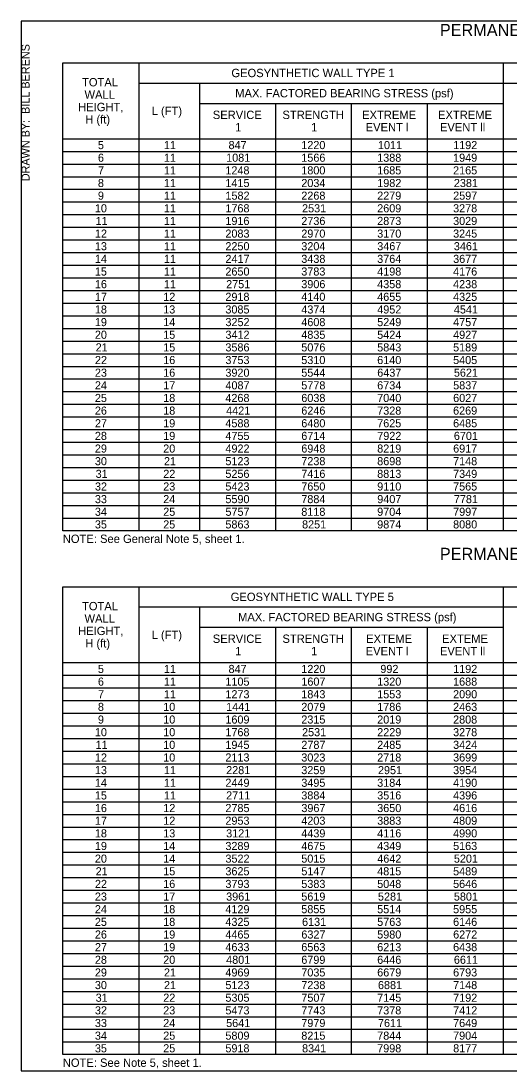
# Model space of a CAD drawing. Extents: x 99862 to 103151, y 100000 to 111076.
# Drawn here: x 99862 to 100828, y 106000 to 108076 of the extents above; entities that cross this region are included whole.
import ezdxf

# ---------------------------------------------------------------- set-up
doc = ezdxf.new("R2010")
doc.units = 0
for name, color, linetype in [('Level 1', 7, 'Continuous'), ('Level 20', 7, 'Continuous'), ('Level 40', 7, 'Continuous'), ('Level 60', 7, 'Continuous'), ('Level 62', 7, 'Continuous')]:
    doc.layers.add(name, color=color, linetype=linetype)

msp = doc.modelspace()

# ---------------------------------------------------------------- linework, layer by layer
at = {"layer": 'Level 1'}
msp.add_lwpolyline([(99862, 105999.5), (103151, 105999.5), (103151, 108075.5), (99862, 108075.5)], close=True, dxfattribs=at)
at = {"layer": 'Level 40'}
for p, q in [((100094.6, 107992.7), (100094.6, 107067.7)), ((100814.6, 107992.7), (100814.6, 107067.7)), ((100094.6, 107952.7), (102524.6, 107952.7)), ((100214.6, 107952.7), (100214.6, 107067.7)), ((100214.6, 107912.7), (100814.6, 107912.7)), ((100364.6, 107912.7), (100364.6, 107067.7)), ((100514.6, 107912.7), (100514.6, 107067.7)), ((100664.6, 107912.7), (100664.6, 107067.7)), ((99944.6, 107842.7), (102524.6, 107842.7)), ((99944.6, 107817.7), (102524.6, 107817.7)), ((99944.6, 107792.7), (102524.6, 107792.7)), ((99944.6, 107767.7), (102524.6, 107767.7)), ((99944.6, 107742.7), (102524.6, 107742.7)), ((99944.6, 107717.7), (102524.6, 107717.7)), ((99944.6, 107692.7), (102524.6, 107692.7)), ((99944.6, 107667.7), (102524.6, 107667.7)), ((99944.6, 107642.7), (102524.6, 107642.7)), ((99944.6, 107617.7), (102524.6, 107617.7)), ((99944.6, 107592.7), (102524.6, 107592.7)), ((99944.6, 107567.7), (102524.6, 107567.7)), ((99944.6, 107542.7), (102524.6, 107542.7)), ((99944.6, 107517.7), (102524.6, 107517.7)), ((99944.6, 107492.7), (102524.6, 107492.7)), ((99944.6, 107467.7), (102524.6, 107467.7)), ((99944.6, 107442.7), (102524.6, 107442.7)), ((99944.6, 107417.7), (102524.6, 107417.7)), ((99944.6, 107392.7), (102524.6, 107392.7)), ((99944.6, 107367.7), (102524.6, 107367.7)), ((99944.6, 107342.7), (102524.6, 107342.7)), ((99944.6, 107317.7), (102524.6, 107317.7)), ((99944.6, 107292.7), (102524.6, 107292.7)), ((99944.6, 107267.7), (102524.6, 107267.7)), ((99944.6, 107242.7), (102524.6, 107242.7)), ((99944.6, 107217.7), (102524.6, 107217.7)), ((99944.6, 107192.7), (102524.6, 107192.7)), ((99944.6, 107167.7), (102524.6, 107167.7)), ((99944.6, 107142.7), (102524.6, 107142.7)), ((99944.6, 107117.7), (102524.6, 107117.7)), ((99944.6, 107092.7), (102524.6, 107092.7)), ((100094.6, 106956.9), (100094.6, 106031.9)), ((100814.6, 106956.9), (100814.6, 106031.9)), ((100094.6, 106916.9), (102524.6, 106916.9)), ((100214.6, 106916.9), (100214.6, 106031.9)), ((100214.6, 106876.9), (100814.6, 106876.9)), ((100364.6, 106876.9), (100364.6, 106031.9)), ((100514.6, 106876.9), (100514.6, 106031.9)), ((100664.6, 106876.9), (100664.6, 106031.9)), ((99944.6, 106806.9), (102524.6, 106806.9)), ((99944.6, 106781.9), (102524.6, 106781.9)), ((99944.6, 106756.9), (102524.6, 106756.9)), ((99944.6, 106731.9), (102524.6, 106731.9)), ((99944.6, 106706.9), (102524.6, 106706.9)), ((99944.6, 106681.9), (102524.6, 106681.9)), ((99944.6, 106656.9), (102524.6, 106656.9)), ((99944.6, 106631.9), (102524.6, 106631.9)), ((99944.6, 106606.9), (102524.6, 106606.9)), ((99944.6, 106581.9), (102524.6, 106581.9)), ((99944.6, 106556.9), (102524.6, 106556.9)), ((99944.6, 106531.9), (102524.6, 106531.9)), ((99944.6, 106506.9), (102524.6, 106506.9)), ((99944.6, 106481.9), (102524.6, 106481.9)), ((99944.6, 106456.9), (102524.6, 106456.9)), ((99944.6, 106431.9), (102524.6, 106431.9)), ((99944.6, 106406.9), (102524.6, 106406.9)), ((99944.6, 106381.9), (102524.6, 106381.9)), ((99944.6, 106356.9), (102524.6, 106356.9)), ((99944.6, 106331.9), (102524.6, 106331.9)), ((99944.6, 106306.9), (102524.6, 106306.9)), ((99944.6, 106281.9), (102524.6, 106281.9)), ((99944.6, 106256.9), (102524.6, 106256.9)), ((99944.6, 106231.9), (102524.6, 106231.9)), ((99944.6, 106206.9), (102524.6, 106206.9)), ((99944.6, 106181.9), (102524.6, 106181.9)), ((99944.6, 106156.9), (102524.6, 106156.9)), ((99944.6, 106131.9), (102524.6, 106131.9)), ((99944.6, 106106.9), (102524.6, 106106.9)), ((99944.6, 106081.9), (102524.6, 106081.9)), ((99944.6, 106056.9), (102524.6, 106056.9))]:
    msp.add_line(p, q, dxfattribs=at)
for points in [[(99944.6, 107992.7), (102524.6, 107992.7), (102524.6, 107067.7), (99944.6, 107067.7)], [(99944.6, 106956.9), (102524.6, 106956.9), (102524.6, 106031.9), (99944.6, 106031.9)]]:
    msp.add_lwpolyline(points, close=True, dxfattribs=at)
at = {"layer": 'Level 60'}
msp.add_line((99862, 105999.5), (99862, 105999.5), dxfattribs=at)

# ---------------------------------------------------------------- texts
at = {"layer": 'Level 20'}
for s, height, p in [('PERMANENT GEOSYNTHETIC WALL - EXTERNAL STABILITY DESIGN', 24, (100689.7, 108045.7)), ('GEOSYNTHETIC WALL TYPE 1', 16.5, (100277.8, 107964.5)), ('TOTAL', 16.5, (99982.6, 107946.2)), ('WALL', 16.5, (99987.5, 107921.7)), ('MAX. FACTORED BEARING STRESS (psf)', 16.5, (100285.3, 107924.5)), ('HEIGHT,', 16.5, (99974.9, 107897.2)), ('H (ft)', 16.5, (99989, 107872.7)), ('L (FT)', 16.5, (100120.2, 107889.5)), ('SERVICE', 16.5, (100241, 107881.7)), ('STRENGTH', 16.5, (100378.7, 107881.7)), ('EXTREME', 16.5, (100536.1, 107881.7)), ('EXTREME', 16.5, (100686.1, 107881.7)), ('1', 16.5, (100285.2, 107857.2)), ('1', 16.5, (100435.2, 107857.2)), ('EVENT l', 16.5, (100543.1, 107857.2)), ('EVENT ll', 16.5, (100689.9, 107857.2)), ('5', 16, (100014, 107822.2)), ('11', 16, (100144.5, 107822.2)), ('847', 16, (100272.1, 107822.2)), ('1220', 16, (100415.9, 107822.2)), ('1011', 16, (100567.4, 107822.2)), ('1192', 16, (100716, 107822.2)), ('6', 16, (100014, 107797.2)), ('11', 16, (100144.5, 107797.2)), ('1081', 16, (100267.4, 107797.2)), ('1566', 16, (100415.9, 107797.2)), ('1388', 16, (100565.9, 107797.2)), ('1949', 16, (100715.9, 107797.2)), ('7', 16, (100014.2, 107772.2)), ('11', 16, (100144.5, 107772.2)), ('1248', 16, (100265.9, 107772.2)), ('1800', 16, (100415.9, 107772.2)), ('1685', 16, (100565.9, 107772.2)), ('2165', 16, (100715.9, 107772.2)), ('8', 16, (100014, 107747.2)), ('11', 16, (100144.5, 107747.2)), ('1415', 16, (100265.9, 107747.2)), ('2034', 16, (100415.9, 107747.2)), ('1982', 16, (100566, 107747.2)), ('2381', 16, (100717.4, 107747.2)), ('9', 16, (100014, 107722.2)), ('11', 16, (100144.5, 107722.2)), ('1582', 16, (100266, 107722.2)), ('2268', 16, (100415.9, 107722.2)), ('2279', 16, (100565.9, 107722.2)), ('2597', 16, (100716, 107722.2)), ('10', 16, (100008, 107697.2)), ('11', 16, (100144.5, 107697.2)), ('1768', 16, (100265.9, 107697.2)), ('2531', 16, (100417.4, 107697.2)), ('2609', 16, (100565.9, 107697.2)), ('3278', 16, (100715.9, 107697.2)), ('11', 16, (100009.5, 107672.2)), ('11', 16, (100144.5, 107672.2)), ('1916', 16, (100265.9, 107672.2)), ('2736', 16, (100415.9, 107672.2)), ('2873', 16, (100565.9, 107672.2)), ('3029', 16, (100715.9, 107672.2)), ('12', 16, (100008.1, 107647.2)), ('11', 16, (100144.5, 107647.2)), ('2083', 16, (100265.9, 107647.2)), ('2970', 16, (100415.9, 107647.2)), ('3170', 16, (100565.9, 107647.2)), ('3245', 16, (100715.9, 107647.2)), ('13', 16, (100008, 107622.2)), ('11', 16, (100144.5, 107622.2)), ('2250', 16, (100265.9, 107622.2)), ('3204', 16, (100415.9, 107622.2)), ('3467', 16, (100566, 107622.2)), ('3461', 16, (100717.4, 107622.2)), ('14', 16, (100008, 107597.2)), ('11', 16, (100144.5, 107597.2)), ('2417', 16, (100266, 107597.2)), ('3438', 16, (100415.9, 107597.2)), ('3764', 16, (100565.9, 107597.2)), ('3677', 16, (100716, 107597.2)), ('15', 16, (100008, 107572.2)), ('11', 16, (100144.5, 107572.2)), ('2650', 16, (100265.9, 107572.2)), ('3783', 16, (100415.9, 107572.2)), ('4198', 16, (100565.9, 107572.2)), ('4176', 16, (100715.9, 107572.2)), ('16', 16, (100008, 107547.2)), ('11', 16, (100144.5, 107547.2)), ('2751', 16, (100267.4, 107547.2)), ('3906', 16, (100415.9, 107547.2)), ('4358', 16, (100565.9, 107547.2)), ('4238', 16, (100715.9, 107547.2)), ('17', 16, (100008.1, 107522.2)), ('12', 16, (100143.1, 107522.2)), ('2918', 16, (100265.9, 107522.2)), ('4140', 16, (100415.9, 107522.2)), ('4655', 16, (100565.9, 107522.2)), ('4325', 16, (100715.9, 107522.2)), ('18', 16, (100008, 107497.2)), ('13', 16, (100143, 107497.2)), ('3085', 16, (100265.9, 107497.2)), ('4374', 16, (100415.9, 107497.2)), ('4952', 16, (100566, 107497.2)), ('4541', 16, (100717.4, 107497.2)), ('19', 16, (100008, 107472.2)), ('14', 16, (100143, 107472.2)), ('3252', 16, (100266, 107472.2)), ('4608', 16, (100415.9, 107472.2)), ('5249', 16, (100565.9, 107472.2)), ('4757', 16, (100716, 107472.2)), ('20', 16, (100008, 107447.2)), ('15', 16, (100143, 107447.2)), ('3412', 16, (100266, 107447.2)), ('4835', 16, (100415.9, 107447.2)), ('5424', 16, (100565.9, 107447.2)), ('4927', 16, (100716, 107447.2)), ('21', 16, (100009.5, 107422.2)), ('15', 16, (100143, 107422.2)), ('3586', 16, (100265.9, 107422.2)), ('5076', 16, (100415.9, 107422.2)), ('5843', 16, (100565.9, 107422.2)), ('5189', 16, (100715.9, 107422.2)), ('22', 16, (100008.1, 107397.2)), ('16', 16, (100143, 107397.2)), ('3753', 16, (100265.9, 107397.2)), ('5310', 16, (100415.9, 107397.2)), ('6140', 16, (100565.9, 107397.2)), ('5405', 16, (100715.9, 107397.2)), ('23', 16, (100008, 107372.2)), ('16', 16, (100143, 107372.2)), ('3920', 16, (100265.9, 107372.2)), ('5544', 16, (100415.9, 107372.2)), ('6437', 16, (100566, 107372.2)), ('5621', 16, (100717.4, 107372.2)), ('24', 16, (100008, 107347.2)), ('17', 16, (100143.1, 107347.2)), ('4087', 16, (100266, 107347.2)), ('5778', 16, (100415.9, 107347.2)), ('6734', 16, (100565.9, 107347.2)), ('5837', 16, (100716, 107347.2)), ('25', 16, (100008, 107322.2)), ('18', 16, (100143, 107322.2)), ('4268', 16, (100265.9, 107322.2)), ('6038', 16, (100415.9, 107322.2)), ('7040', 16, (100565.9, 107322.2)), ('6027', 16, (100716, 107322.2)), ('26', 16, (100008, 107297.2)), ('18', 16, (100143, 107297.2)), ('4421', 16, (100267.4, 107297.2)), ('6246', 16, (100415.9, 107297.2)), ('7328', 16, (100565.9, 107297.2)), ('6269', 16, (100715.9, 107297.2)), ('27', 16, (100008.1, 107272.2)), ('19', 16, (100143, 107272.2)), ('4588', 16, (100265.9, 107272.2)), ('6480', 16, (100415.9, 107272.2)), ('7625', 16, (100565.9, 107272.2)), ('6485', 16, (100715.9, 107272.2)), ('28', 16, (100008, 107247.2)), ('19', 16, (100143, 107247.2)), ('4755', 16, (100265.9, 107247.2)), ('6714', 16, (100415.9, 107247.2)), ('7922', 16, (100566, 107247.2)), ('6701', 16, (100717.4, 107247.2)), ('29', 16, (100008, 107222.2)), ('20', 16, (100143, 107222.2)), ('4922', 16, (100266, 107222.2)), ('6948', 16, (100415.9, 107222.2)), ('8219', 16, (100565.9, 107222.2)), ('6917', 16, (100716, 107222.2)), ('30', 16, (100008, 107197.2)), ('21', 16, (100144.5, 107197.2)), ('5123', 16, (100265.9, 107197.2)), ('7238', 16, (100415.9, 107197.2)), ('8698', 16, (100565.9, 107197.2)), ('7148', 16, (100715.9, 107197.2)), ('31', 16, (100009.5, 107172.2)), ('22', 16, (100143.1, 107172.2)), ('5256', 16, (100265.9, 107172.2)), ('7416', 16, (100415.9, 107172.2)), ('8813', 16, (100565.9, 107172.2)), ('7349', 16, (100715.9, 107172.2)), ('32', 16, (100008.1, 107147.2)), ('23', 16, (100143, 107147.2)), ('5423', 16, (100265.9, 107147.2)), ('7650', 16, (100415.9, 107147.2)), ('9110', 16, (100565.9, 107147.2)), ('7565', 16, (100715.9, 107147.2)), ('33', 16, (100008, 107122.2)), ('24', 16, (100143, 107122.2)), ('5590', 16, (100265.9, 107122.2)), ('7884', 16, (100415.9, 107122.2)), ('9407', 16, (100566, 107122.2)), ('7781', 16, (100717.4, 107122.2)), ('34', 16, (100008, 107097.2)), ('25', 16, (100143, 107097.2)), ('5757', 16, (100266, 107097.2)), ('8118', 16, (100415.9, 107097.2)), ('9704', 16, (100565.9, 107097.2)), ('7997', 16, (100716, 107097.2)), ('35', 16, (100008, 107072.2)), ('25', 16, (100143, 107072.2)), ('5863', 16, (100265.9, 107072.2)), ('8251', 16, (100417.4, 107072.2)), ('9874', 16, (100565.9, 107072.2)), ('8080', 16, (100715.9, 107072.2)), ('NOTE: See General Note 5, sheet 1.', 16.5, (99944.6, 107043.5)), ('PERMANENT GEOSYNTHETIC WALL - EXTERNAL STABILITY DESIGN', 24, (100689.7, 107009.9)), ('GEOSYNTHETIC WALL TYPE 5', 16.5, (100276.4, 106928.7)), ('TOTAL', 16.5, (99982.6, 106910.4)), ('WALL', 16.5, (99987.5, 106885.9)), ('MAX. FACTORED BEARING STRESS (psf)', 16.5, (100291, 106888.7)), ('HEIGHT,', 16.5, (99974.9, 106861.4)), ('H (ft)', 16.5, (99989, 106836.9)), ('L (FT)', 16.5, (100120.2, 106853.7)), ('SERVICE', 16.5, (100241, 106845.9)), ('STRENGTH', 16.5, (100378.7, 106845.9)), ('EXTEME', 16.5, (100544.1, 106845.9)), ('EXTEME', 16.5, (100694.1, 106845.9)), ('1', 16.5, (100285.2, 106821.4)), ('1', 16.5, (100435.2, 106821.4)), ('EVENT l', 16.5, (100543.1, 106821.4)), ('EVENT ll', 16.5, (100689.9, 106821.4)), ('5', 16, (100014, 106786.4)), ('11', 16, (100144.5, 106786.4)), ('847', 16, (100272.1, 106786.4)), ('1220', 16, (100415.9, 106786.4)), ('992', 16, (100572.1, 106786.4)), ('1192', 16, (100716, 106786.4)), ('6', 16, (100014, 106761.4)), ('11', 16, (100144.5, 106761.4)), ('1105', 16, (100265.9, 106761.4)), ('1607', 16, (100416, 106761.4)), ('1320', 16, (100565.9, 106761.4)), ('1688', 16, (100715.9, 106761.4)), ('7', 16, (100014.2, 106736.4)), ('11', 16, (100144.5, 106736.4)), ('1273', 16, (100265.9, 106736.4)), ('1843', 16, (100415.9, 106736.4)), ('1553', 16, (100565.9, 106736.4)), ('2090', 16, (100715.9, 106736.4)), ('8', 16, (100014, 106711.4)), ('10', 16, (100143, 106711.4)), ('1441', 16, (100267.4, 106711.4)), ('2079', 16, (100415.9, 106711.4)), ('1786', 16, (100565.9, 106711.4)), ('2463', 16, (100715.9, 106711.4)), ('9', 16, (100014, 106686.4)), ('10', 16, (100143, 106686.4)), ('1609', 16, (100265.9, 106686.4)), ('2315', 16, (100415.9, 106686.4)), ('2019', 16, (100565.9, 106686.4)), ('2808', 16, (100715.9, 106686.4)), ('10', 16, (100008, 106661.4)), ('10', 16, (100143, 106661.4)), ('1768', 16, (100265.9, 106661.4)), ('2531', 16, (100417.4, 106661.4)), ('2229', 16, (100565.9, 106661.4)), ('3278', 16, (100715.9, 106661.4)), ('11', 16, (100009.5, 106636.4)), ('10', 16, (100143, 106636.4)), ('1945', 16, (100265.9, 106636.4)), ('2787', 16, (100416, 106636.4)), ('2485', 16, (100565.9, 106636.4)), ('3424', 16, (100715.9, 106636.4)), ('12', 16, (100008.1, 106611.4)), ('10', 16, (100143, 106611.4)), ('2113', 16, (100265.9, 106611.4)), ('3023', 16, (100415.9, 106611.4)), ('2718', 16, (100565.9, 106611.4)), ('3699', 16, (100715.9, 106611.4)), ('13', 16, (100008, 106586.4)), ('2281', 16, (100267.4, 106586.4)), ('3259', 16, (100415.9, 106586.4)), ('2951', 16, (100567.4, 106586.4)), ('3954', 16, (100715.9, 106586.4)), ('11', 16, (100144.5, 106586.4)), ('14', 16, (100008, 106561.4)), ('11', 16, (100144.5, 106561.4)), ('2449', 16, (100265.9, 106561.4)), ('3495', 16, (100415.9, 106561.4)), ('3184', 16, (100565.9, 106561.4)), ('4190', 16, (100715.9, 106561.4)), ('15', 16, (100008, 106536.4)), ('11', 16, (100144.5, 106536.4)), ('2711', 16, (100267.4, 106536.4)), ('3884', 16, (100415.9, 106536.4)), ('3516', 16, (100565.9, 106536.4)), ('4396', 16, (100715.9, 106536.4)), ('16', 16, (100008, 106511.4)), ('12', 16, (100143.1, 106511.4)), ('2785', 16, (100265.9, 106511.4)), ('3967', 16, (100416, 106511.4)), ('3650', 16, (100565.9, 106511.4)), ('4616', 16, (100715.9, 106511.4)), ('17', 16, (100008.1, 106486.4)), ('12', 16, (100143.1, 106486.4)), ('2953', 16, (100265.9, 106486.4)), ('4203', 16, (100415.9, 106486.4)), ('3883', 16, (100565.9, 106486.4)), ('4809', 16, (100715.9, 106486.4)), ('18', 16, (100008, 106461.4)), ('13', 16, (100143, 106461.4)), ('3121', 16, (100267.4, 106461.4)), ('4439', 16, (100415.9, 106461.4)), ('4116', 16, (100565.9, 106461.4)), ('4990', 16, (100715.9, 106461.4)), ('19', 16, (100008, 106436.4)), ('14', 16, (100143, 106436.4)), ('3289', 16, (100265.9, 106436.4)), ('4675', 16, (100415.9, 106436.4)), ('4349', 16, (100565.9, 106436.4)), ('5163', 16, (100715.9, 106436.4)), ('20', 16, (100008, 106411.4)), ('14', 16, (100143, 106411.4)), ('3522', 16, (100266, 106411.4)), ('5015', 16, (100415.9, 106411.4)), ('4642', 16, (100566, 106411.4)), ('5201', 16, (100717.4, 106411.4)), ('21', 16, (100009.5, 106386.4)), ('15', 16, (100143, 106386.4)), ('3625', 16, (100265.9, 106386.4)), ('5147', 16, (100416, 106386.4)), ('4815', 16, (100565.9, 106386.4)), ('5489', 16, (100715.9, 106386.4)), ('22', 16, (100008.1, 106361.4)), ('16', 16, (100143, 106361.4)), ('3793', 16, (100265.9, 106361.4)), ('5383', 16, (100415.9, 106361.4)), ('5048', 16, (100565.9, 106361.4)), ('5646', 16, (100715.9, 106361.4)), ('23', 16, (100008, 106336.4)), ('17', 16, (100143.1, 106336.4)), ('3961', 16, (100267.4, 106336.4)), ('5619', 16, (100415.9, 106336.4)), ('5281', 16, (100567.4, 106336.4)), ('5801', 16, (100717.4, 106336.4)), ('24', 16, (100008, 106311.4)), ('18', 16, (100143, 106311.4)), ('4129', 16, (100265.9, 106311.4)), ('5855', 16, (100415.9, 106311.4)), ('5514', 16, (100565.9, 106311.4)), ('5955', 16, (100715.9, 106311.4)), ('25', 16, (100008, 106286.4)), ('18', 16, (100143, 106286.4)), ('4325', 16, (100265.9, 106286.4)), ('6131', 16, (100417.4, 106286.4)), ('5763', 16, (100565.9, 106286.4)), ('6146', 16, (100715.9, 106286.4)), ('26', 16, (100008, 106261.4)), ('19', 16, (100143, 106261.4)), ('4465', 16, (100265.9, 106261.4)), ('6327', 16, (100416, 106261.4)), ('5980', 16, (100565.9, 106261.4)), ('6272', 16, (100716, 106261.4)), ('27', 16, (100008.1, 106236.4)), ('19', 16, (100143, 106236.4)), ('4633', 16, (100265.9, 106236.4)), ('6563', 16, (100415.9, 106236.4)), ('6213', 16, (100565.9, 106236.4)), ('6438', 16, (100715.9, 106236.4)), ('28', 16, (100008, 106211.4)), ('20', 16, (100143, 106211.4)), ('4801', 16, (100267.4, 106211.4)), ('6799', 16, (100415.9, 106211.4)), ('6446', 16, (100565.9, 106211.4)), ('6611', 16, (100717.4, 106211.4)), ('29', 16, (100008, 106186.4)), ('21', 16, (100144.5, 106186.4)), ('4969', 16, (100265.9, 106186.4)), ('7035', 16, (100415.9, 106186.4)), ('6679', 16, (100565.9, 106186.4)), ('6793', 16, (100715.9, 106186.4)), ('30', 16, (100008, 106161.4)), ('21', 16, (100144.5, 106161.4)), ('5123', 16, (100265.9, 106161.4)), ('7238', 16, (100415.9, 106161.4)), ('6881', 16, (100567.4, 106161.4)), ('7148', 16, (100715.9, 106161.4)), ('31', 16, (100009.5, 106136.4)), ('22', 16, (100143.1, 106136.4)), ('5305', 16, (100265.9, 106136.4)), ('7507', 16, (100416, 106136.4)), ('7145', 16, (100565.9, 106136.4)), ('7192', 16, (100716, 106136.4)), ('32', 16, (100008.1, 106111.4)), ('23', 16, (100143, 106111.4)), ('5473', 16, (100265.9, 106111.4)), ('7743', 16, (100415.9, 106111.4)), ('7378', 16, (100565.9, 106111.4)), ('7412', 16, (100716, 106111.4)), ('33', 16, (100008, 106086.4)), ('24', 16, (100143, 106086.4)), ('5641', 16, (100267.4, 106086.4)), ('7979', 16, (100415.9, 106086.4)), ('7611', 16, (100567.4, 106086.4)), ('7649', 16, (100715.9, 106086.4)), ('34', 16, (100008, 106061.4)), ('25', 16, (100143, 106061.4)), ('5809', 16, (100265.9, 106061.4)), ('8215', 16, (100415.9, 106061.4)), ('7844', 16, (100565.9, 106061.4)), ('7904', 16, (100715.9, 106061.4)), ('35', 16, (100008, 106036.4)), ('25', 16, (100143, 106036.4)), ('5918', 16, (100265.9, 106036.4)), ('8341', 16, (100417.4, 106036.4)), ('7998', 16, (100565.9, 106036.4)), ('8177', 16, (100716, 106036.4)), ('NOTE: See Note 5, sheet 1.', 16.5, (99944.6, 106007.7))]:
    msp.add_text(s, height=height, dxfattribs=at).set_placement(p)
at = {"layer": 'Level 62'}
msp.add_text('DRAWN BY:  BILL BERENS', height=16, rotation=90, dxfattribs=at).set_placement((99879, 107758.7))

doc.saveas('drawing.dxf')
